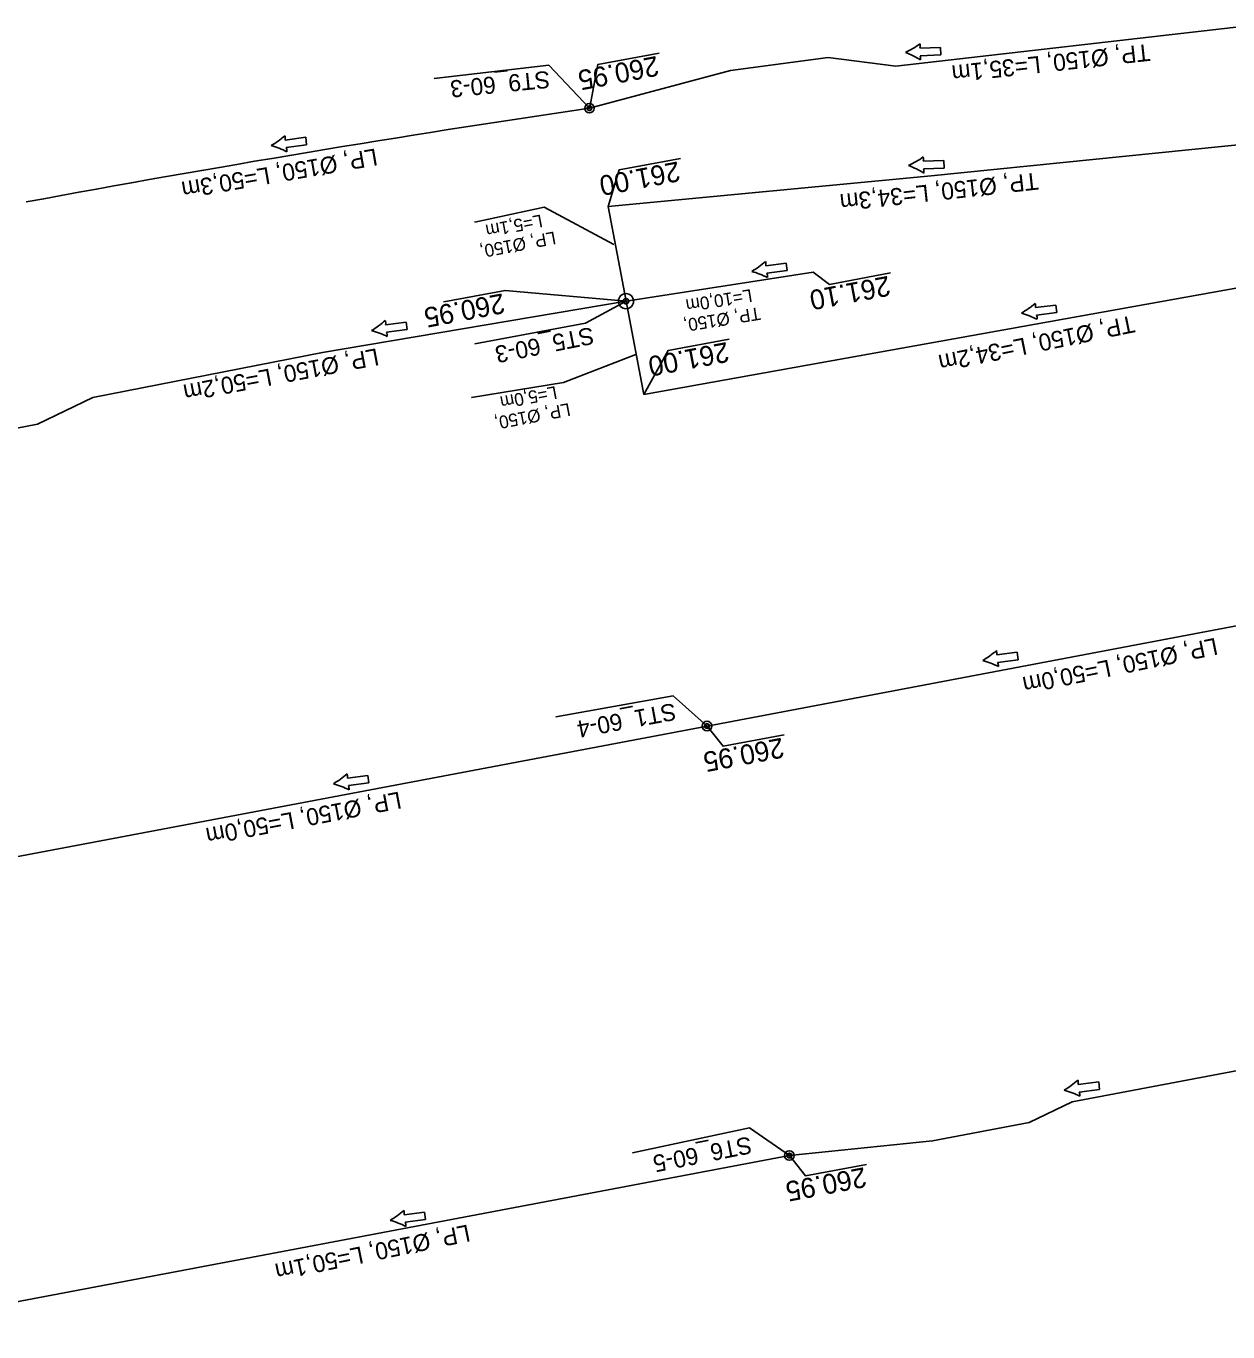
# Model space of a CAD drawing. Extents: x -1 to 65640748, y -22 to 5530284.
# Drawn here: x 6558095 to 6558158.5, y 5528773.5 to 5528842.5 of the extents above; entities that cross this region are included whole.
import ezdxf

# ---------------------------------------------------------------- set-up
doc = ezdxf.new("R2010")
doc.units = 0
for name, color, linetype in [('TOR_PROF-studnie i osadniki', 7, 'Continuous'), ('TOR_PS_ODW-drenaze', 7, 'Continuous'), ('TOR_PS_ODW-drenokolektory', 7, 'Continuous'), ('TOR_PS_ODW-studnie PEHD', 7, 'Continuous'), ('TOR_PS_OPIS_O-opisy rurociagow', 7, 'Continuous'), ('TOR_PS_OPIS_O-opisy studni', 7, 'Continuous'), ('TOR_PS_OPIS_T-INFO', 7, 'Continuous')]:
    doc.layers.add(name, color=color, linetype=linetype)

msp = doc.modelspace()

# ---------------------------------------------------------------- linework, layer by layer
at = {"layer": 'TOR_PROF-studnie i osadniki'}
for centre, radius in [((6558124.752, 5528838.168), 0.25), ((6558124.752, 5528838.168), 0.125), ((6558130.962, 5528805.531), 0.25), ((6558130.962, 5528805.531), 0.125), ((6558135.31, 5528782.843), 0.25), ((6558135.31, 5528782.843), 0.125)]:
    msp.add_circle(centre, radius, dxfattribs=at)
at = {"layer": 'TOR_PS_ODW-drenaze'}
for points in [[(6558159.37, 5528842.504), (6558140.943, 5528840.386), (6558137.359, 5528840.849), (6558132.205, 5528840.156), (6558124.752, 5528838.168)], [(6558159.869, 5528836.318), (6558159.869, 5528836.318), (6558142.805, 5528834.603)], [(6558142.805, 5528834.603), (6558125.736, 5528832.978)], [(6558136.571, 5528829.512), (6558126.685, 5528827.972), (6558126.685, 5528827.972)], [(6558161.25, 5528829.08), (6558127.62, 5528823.039)], [(6558186.538, 5528792.554), (6558150.243, 5528785.674), (6558147.981, 5528784.584), (6558142.872, 5528783.615), (6558135.31, 5528782.843)]]:
    msp.add_lwpolyline(points, dxfattribs=at)
at = {"layer": 'TOR_PS_ODW-drenokolektory'}
for p, q in [((6558180.122, 5528814.849), (6558130.962, 5528805.531)), ((6558130.962, 5528805.531), (6558081.814, 5528796.214))]:
    msp.add_line(p, q, dxfattribs=at)
for points in [[(6558126.685, 5528827.972), (6558125.736, 5528832.978)], [(6558126.685, 5528827.972), (6558110.662, 5528825.263), (6558098.518, 5528822.877), (6558095.607, 5528821.474), (6558090.233, 5528820.446), (6558086.884, 5528820.696), (6558077.478, 5528818.998)], [(6558127.62, 5528823.039), (6558126.685, 5528827.972)], [(6558135.31, 5528782.843), (6558086.116, 5528773.526)]]:
    msp.add_lwpolyline(points, dxfattribs=at)
msp.add_arc((6558241.925, 5528042.955), 803.8, 98.382062, 100.531944, dxfattribs=at)
at = {"layer": 'TOR_PS_ODW-studnie PEHD'}
for centre, radius in [((6558124.752, 5528838.168), 0.25), ((6558124.752, 5528838.168), 0.112), ((6558126.685, 5528827.972), 0.4), ((6558126.685, 5528827.972), 0.145), ((6558130.962, 5528805.531), 0.25), ((6558130.962, 5528805.531), 0.112), ((6558135.31, 5528782.843), 0.25), ((6558135.31, 5528782.843), 0.112)]:
    msp.add_circle(centre, radius, dxfattribs=at)
at = {"layer": 'TOR_PS_OPIS_O-opisy rurociagow'}
for p, q in [((6558143.297, 5528841.38), (6558142.205, 5528841.34)), ((6558142.205, 5528841.34), (6558143.297, 5528841.38)), ((6558143.312, 5528840.98), (6558143.297, 5528841.38)), ((6558143.312, 5528840.98), (6558143.297, 5528841.38)), ((6558142.22, 5528840.94), (6558143.312, 5528840.98)), ((6558142.22, 5528840.94), (6558143.312, 5528840.98)), ((6558109.767, 5528836.629), (6558108.683, 5528836.487)), ((6558108.683, 5528836.487), (6558109.767, 5528836.629)), ((6558109.818, 5528836.232), (6558109.767, 5528836.629)), ((6558109.818, 5528836.232), (6558109.767, 5528836.629)), ((6558108.735, 5528836.091), (6558109.818, 5528836.232)), ((6558108.735, 5528836.091), (6558109.818, 5528836.232)), ((6558143.467, 5528835.408), (6558142.375, 5528835.368)), ((6558142.375, 5528835.368), (6558143.467, 5528835.408)), ((6558142.39, 5528834.968), (6558143.482, 5528835.008)), ((6558142.39, 5528834.968), (6558143.482, 5528835.008)), ((6558143.482, 5528835.008), (6558143.467, 5528835.408)), ((6558143.482, 5528835.008), (6558143.467, 5528835.408)), ((6558135.148, 5528829.985), (6558134.065, 5528829.844)), ((6558134.065, 5528829.844), (6558135.148, 5528829.985)), ((6558134.116, 5528829.447), (6558135.2, 5528829.589)), ((6558134.116, 5528829.447), (6558135.2, 5528829.589)), ((6558135.2, 5528829.589), (6558135.148, 5528829.985)), ((6558135.2, 5528829.589), (6558135.148, 5528829.985)), ((6558149.391, 5528827.771), (6558148.307, 5528827.634)), ((6558148.307, 5528827.634), (6558149.391, 5528827.771)), ((6558148.357, 5528827.237), (6558149.441, 5528827.374)), ((6558148.357, 5528827.237), (6558149.441, 5528827.374)), ((6558149.441, 5528827.374), (6558149.391, 5528827.771)), ((6558149.441, 5528827.374), (6558149.391, 5528827.771)), ((6558115.071, 5528826.867), (6558113.988, 5528826.725)), ((6558113.988, 5528826.725), (6558115.071, 5528826.867)), ((6558115.123, 5528826.47), (6558115.071, 5528826.867)), ((6558115.123, 5528826.47), (6558115.071, 5528826.867)), ((6558114.04, 5528826.329), (6558115.123, 5528826.47)), ((6558114.04, 5528826.329), (6558115.123, 5528826.47)), ((6558147.345, 5528809.426), (6558146.261, 5528809.289)), ((6558146.261, 5528809.289), (6558147.345, 5528809.426)), ((6558147.395, 5528809.029), (6558147.345, 5528809.426)), ((6558147.395, 5528809.029), (6558147.345, 5528809.426)), ((6558146.311, 5528808.892), (6558147.395, 5528809.029)), ((6558146.311, 5528808.892), (6558147.395, 5528809.029)), ((6558113.053, 5528802.92), (6558111.97, 5528802.779)), ((6558111.97, 5528802.779), (6558113.053, 5528802.92)), ((6558112.021, 5528802.382), (6558113.105, 5528802.524)), ((6558112.021, 5528802.382), (6558113.105, 5528802.524)), ((6558113.105, 5528802.524), (6558113.053, 5528802.92)), ((6558113.105, 5528802.524), (6558113.053, 5528802.92)), ((6558151.647, 5528786.73), (6558150.563, 5528786.593)), ((6558150.563, 5528786.593), (6558151.647, 5528786.73)), ((6558151.697, 5528786.333), (6558151.647, 5528786.73)), ((6558151.697, 5528786.333), (6558151.647, 5528786.73)), ((6558150.613, 5528786.196), (6558151.697, 5528786.333)), ((6558150.613, 5528786.196), (6558151.697, 5528786.333)), ((6558116.051, 5528779.856), (6558114.968, 5528779.715)), ((6558114.968, 5528779.715), (6558116.051, 5528779.856)), ((6558116.103, 5528779.46), (6558116.051, 5528779.856)), ((6558116.103, 5528779.46), (6558116.051, 5528779.856)), ((6558115.019, 5528779.318), (6558116.103, 5528779.46)), ((6558115.019, 5528779.318), (6558116.103, 5528779.46))]:
    msp.add_line(p, q, dxfattribs=at)
for points in [[(6558142.207, 5528841.565), (6558142.207, 5528841.565)], [(6558142.238, 5528840.716), (6558142.238, 5528840.716)], [(6558108.664, 5528836.712), (6558108.664, 5528836.712)], [(6558108.774, 5528835.869), (6558108.774, 5528835.869)], [(6558142.377, 5528835.593), (6558142.377, 5528835.593)], [(6558142.409, 5528834.744), (6558142.409, 5528834.744)], [(6558134.046, 5528830.068), (6558134.046, 5528830.068)], [(6558134.156, 5528829.225), (6558134.156, 5528829.225)], [(6558148.289, 5528827.858), (6558148.289, 5528827.858)], [(6558113.969, 5528826.95), (6558113.969, 5528826.95)], [(6558148.395, 5528827.015), (6558148.395, 5528827.015)], [(6558114.079, 5528826.107), (6558114.079, 5528826.107)], [(6558146.243, 5528809.514), (6558146.243, 5528809.514)], [(6558146.35, 5528808.671), (6558146.35, 5528808.671)], [(6558111.951, 5528803.003), (6558111.951, 5528803.003)], [(6558112.061, 5528802.161), (6558112.061, 5528802.161)], [(6558150.545, 5528786.818), (6558150.545, 5528786.818)], [(6558150.652, 5528785.975), (6558150.652, 5528785.975)], [(6558114.949, 5528779.939), (6558114.949, 5528779.939)], [(6558115.059, 5528779.096), (6558115.059, 5528779.096)]]:
    msp.add_lwpolyline(points, dxfattribs=at)
for centre, radius, start, end in [((6558139.329, 5528845.553), 4.918, 295.43746, 305.81928), ((6558139.329, 5528845.553), 4.918, 295.43746, 305.81928), ((6558141.762, 5528841.456), 0.458, 345.24348, 13.70472), ((6558141.762, 5528841.456), 0.458, 345.24348, 13.70472), ((6558139.662, 5528836.527), 4.918, 58.39957, 68.7814), ((6558139.662, 5528836.527), 4.918, 58.39957, 68.7814), ((6558141.787, 5528840.791), 0.458, 350.51413, 18.97537), ((6558141.787, 5528840.791), 0.458, 350.51413, 18.97537), ((6558105.428, 5528840.415), 4.918, 300.76623, 311.14806), ((6558105.428, 5528840.415), 4.918, 300.76623, 311.14806), ((6558108.231, 5528836.562), 0.458, 350.57226, 19.0335), ((6558108.231, 5528836.562), 0.458, 350.57226, 19.0335), ((6558106.598, 5528831.459), 4.918, 63.72835, 74.11017), ((6558106.598, 5528831.459), 4.918, 63.72835, 74.11017), ((6558108.318, 5528835.902), 0.458, 355.84291, 24.30415), ((6558108.318, 5528835.902), 0.458, 355.84291, 24.30415), ((6558139.499, 5528839.58), 4.918, 295.43746, 305.81928), ((6558139.499, 5528839.58), 4.918, 295.43746, 305.81928), ((6558139.832, 5528830.555), 4.918, 58.39957, 68.7814), ((6558139.832, 5528830.555), 4.918, 58.39957, 68.7814), ((6558141.933, 5528835.484), 0.458, 345.24348, 13.70472), ((6558141.933, 5528835.484), 0.458, 345.24348, 13.70472), ((6558141.957, 5528834.819), 0.458, 350.51413, 18.97537), ((6558141.957, 5528834.819), 0.458, 350.51413, 18.97537), ((6558130.81, 5528833.771), 4.918, 300.76623, 311.14806), ((6558130.81, 5528833.771), 4.918, 300.76623, 311.14806), ((6558131.979, 5528824.816), 4.918, 63.72835, 74.11017), ((6558131.979, 5528824.816), 4.918, 63.72835, 74.11017), ((6558133.613, 5528829.919), 0.458, 350.57226, 19.0335), ((6558133.613, 5528829.919), 0.458, 350.57226, 19.0335), ((6558133.699, 5528829.259), 0.458, 355.84291, 24.30415), ((6558133.699, 5528829.259), 0.458, 355.84291, 24.30415), ((6558145.068, 5528831.574), 4.918, 300.53119, 310.91302), ((6558145.068, 5528831.574), 4.918, 300.53119, 310.91302), ((6558146.201, 5528822.614), 4.918, 63.4933, 73.87513), ((6558146.201, 5528822.614), 4.918, 63.4933, 73.87513), ((6558147.855, 5528827.71), 0.458, 350.33722, 18.79846), ((6558147.855, 5528827.71), 0.458, 350.33722, 18.79846), ((6558110.733, 5528830.653), 4.918, 300.76623, 311.14806), ((6558110.733, 5528830.653), 4.918, 300.76623, 311.14806), ((6558113.536, 5528826.8), 0.458, 350.57226, 19.0335), ((6558113.536, 5528826.8), 0.458, 350.57226, 19.0335), ((6558147.939, 5528827.05), 0.458, 355.60787, 24.06911), ((6558147.939, 5528827.05), 0.458, 355.60787, 24.06911), ((6558111.902, 5528821.697), 4.918, 63.72835, 74.11017), ((6558111.902, 5528821.697), 4.918, 63.72835, 74.11017), ((6558113.622, 5528826.14), 0.458, 355.84291, 24.30415), ((6558113.622, 5528826.14), 0.458, 355.84291, 24.30415), ((6558143.022, 5528813.23), 4.918, 300.53119, 310.91302), ((6558143.022, 5528813.23), 4.918, 300.53119, 310.91302), ((6558145.81, 5528809.366), 0.458, 350.33722, 18.79846), ((6558145.81, 5528809.366), 0.458, 350.33722, 18.79846), ((6558144.155, 5528804.27), 4.918, 63.4933, 73.87513), ((6558144.155, 5528804.27), 4.918, 63.4933, 73.87513), ((6558145.893, 5528808.706), 0.458, 355.60787, 24.06911), ((6558145.893, 5528808.706), 0.458, 355.60787, 24.06911), ((6558108.715, 5528806.707), 4.918, 300.76623, 311.14806), ((6558108.715, 5528806.707), 4.918, 300.76623, 311.14806), ((6558111.518, 5528802.854), 0.458, 350.57226, 19.0335), ((6558111.518, 5528802.854), 0.458, 350.57226, 19.0335), ((6558109.884, 5528797.751), 4.918, 63.72835, 74.11017), ((6558109.884, 5528797.751), 4.918, 63.72835, 74.11017), ((6558111.604, 5528802.194), 0.458, 355.84291, 24.30415), ((6558111.604, 5528802.194), 0.458, 355.84291, 24.30415), ((6558147.325, 5528790.534), 4.918, 300.53119, 310.91302), ((6558147.325, 5528790.534), 4.918, 300.53119, 310.91302), ((6558150.112, 5528786.67), 0.458, 350.33722, 18.79846), ((6558150.112, 5528786.67), 0.458, 350.33722, 18.79846), ((6558148.457, 5528781.574), 4.918, 63.4933, 73.87513), ((6558148.457, 5528781.574), 4.918, 63.4933, 73.87513), ((6558150.195, 5528786.01), 0.458, 355.60787, 24.06911), ((6558150.195, 5528786.01), 0.458, 355.60787, 24.06911), ((6558111.713, 5528783.642), 4.918, 300.76623, 311.14806), ((6558111.713, 5528783.642), 4.918, 300.76623, 311.14806), ((6558114.516, 5528779.79), 0.458, 350.57226, 19.0335), ((6558114.516, 5528779.79), 0.458, 350.57226, 19.0335), ((6558112.882, 5528774.687), 4.918, 63.72835, 74.11017), ((6558112.882, 5528774.687), 4.918, 63.72835, 74.11017), ((6558114.602, 5528779.13), 0.458, 355.84291, 24.30415), ((6558114.602, 5528779.13), 0.458, 355.84291, 24.30415)]:
    msp.add_arc(centre, radius, start, end, dxfattribs=at)
at = {"layer": 'TOR_PS_OPIS_T-INFO'}
for points in [[(6558116.558, 5528839.728), (6558116.558, 5528839.728), (6558122.606, 5528840.443), (6558124.752, 5528838.168)], [(6558124.773, 5528838.222), (6558125.192, 5528840.476), (6558128.429, 5528841.079)], [(6558125.736, 5528832.978), (6558126.321, 5528834.905), (6558129.558, 5528835.507)], [(6558118.693, 5528832.15), (6558118.693, 5528832.15), (6558122.369, 5528832.94), (6558126.043, 5528830.972)], [(6558136.571, 5528829.512), (6558137.423, 5528828.86), (6558140.661, 5528829.463)], [(6558117.061, 5528827.937), (6558117.061, 5528827.937), (6558120.298, 5528828.539), (6558126.685, 5528827.972)], [(6558118.709, 5528825.717), (6558118.709, 5528825.717), (6558124.552, 5528826.81), (6558126.685, 5528827.972)], [(6558127.62, 5528823.039), (6558128.903, 5528825.364), (6558132.14, 5528825.966)], [(6558118.526, 5528822.877), (6558118.526, 5528822.877), (6558123.389, 5528823.686), (6558127.212, 5528825.163)], [(6558122.985, 5528806.022), (6558122.985, 5528806.022), (6558129.168, 5528807.123), (6558130.962, 5528805.531)], [(6558130.962, 5528805.531), (6558131.808, 5528804.461), (6558135.045, 5528805.063)], [(6558127.029, 5528782.986), (6558127.029, 5528782.986), (6558133.212, 5528784.304), (6558135.31, 5528782.843)], [(6558135.31, 5528782.843), (6558136.156, 5528781.774), (6558139.394, 5528782.376)]]:
    msp.add_lwpolyline(points, dxfattribs=at)

# ---------------------------------------------------------------- texts
at = {"layer": 'TOR_PS_OPIS_O-opisy rurociagow'}
for s, height, rotation, p in [('TP, Ø150, L=35,1m', 0.9, 186.27954, (6558154.314, 5528841.571)), ('LP, Ø150, L=50,3m', 0.9, 189.80577, (6558113.468, 5528836.051)), ('TP, Ø150, L=34,3m', 0.9, 186.27954, (6558148.407, 5528834.772)), ('L=5,1m', 0.675, 190.73252, (6558122.202, 5528832.561)), ('LP, Ø150,', 0.675, 190.73252, (6558122.906, 5528831.664)), ('L=10,0m', 0.675, 189.16713, (6558133.289, 5528828.62)), ('TP, Ø150,', 0.675, 189.16713, (6558133.736, 5528827.667)), ('TP, Ø150, L=34,2m', 0.9, 191.56565, (6558153.442, 5528827.228)), ('LP, Ø150, L=50,2m', 0.9, 190.73763, (6558113.529, 5528825.496)), ('L=5,0m', 0.675, 190.73252, (6558122.969, 5528823.496)), ('LP, Ø150,', 0.675, 190.73252, (6558123.674, 5528822.599)), ('LP, Ø150, L=50,0m', 0.9, 191.56565, (6558157.822, 5528810.201)), ('LP, Ø150, L=50,0m', 0.9, 190.73763, (6558114.719, 5528802.076)), ('LP, Ø150, L=50,1m', 0.9, 191.56565, (6558118.341, 5528779.208))]:
    msp.add_text(s, height=height, rotation=rotation, dxfattribs=at).set_placement(p)
at = {"layer": 'TOR_PS_OPIS_O-opisy studni'}
for s, rotation, p in [('ST9_60-3', 185.71516, (6558122.623, 5528840.147)), ('ST5_60-3', 191.40649, (6558124.891, 5528826.62)), ('ST1_60-4', 190.57374, (6558129.233, 5528806.756)), ('ST6_60-5', 191.27037, (6558133.229, 5528783.862))]:
    msp.add_text(s, height=0.9, rotation=rotation, dxfattribs=at).set_placement(p)
at = {"layer": 'TOR_PS_OPIS_T-INFO'}
for s, p in [('260.95', (6558128.302, 5528840.935)), ('261.00', (6558129.428, 5528835.363)), ('261.10', (6558140.531, 5528829.319)), ('260.95', (6558120.171, 5528828.396)), ('261.00', (6558132.01, 5528825.822)), ('260.95', (6558134.918, 5528804.92)), ('260.95', (6558139.266, 5528782.232))]:
    msp.add_text(s, height=1.05, rotation=190.75061, dxfattribs=at).set_placement(p)

doc.saveas('drawing.dxf')
